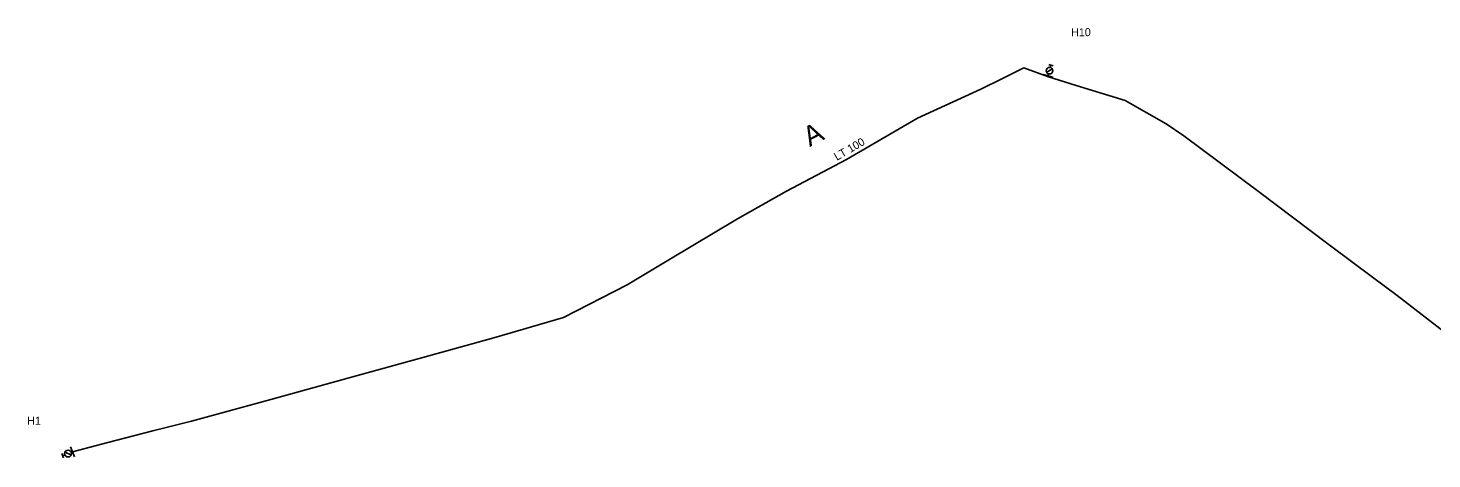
# Model space of a CAD drawing. Extents: x -574447 to -573745, y -1188179 to -1187219.
# Drawn here: x -574446.6 to -574095.8, y -1188024.4 to -1187916.7 of the extents above; entities that cross this region are included whole.
import ezdxf

# ---------------------------------------------------------------- set-up
doc = ezdxf.new("R2010")
doc.units = 0
for name, color, linetype in [('Vrstva 1', 7, 'Continuous'), ('Vrstva 15', 7, 'Continuous'), ('Vrstva 25', 7, 'Continuous'), ('Vrstva 29', 7, 'Continuous'), ('Vrstva 35', 7, 'Continuous')]:
    doc.layers.add(name, color=color, linetype=linetype)

# ---------------------------------------------------------------- blocks, each defined once
blk = doc.blocks.new('160')
at = {"layer": 'Vrstva 1'}
blk.add_circle((0, 0), 0.0458, dxfattribs=at)
blk = doc.blocks.new('133')
at = {"layer": 'Vrstva 1'}
for p, q in [((0.28, 0), (0, 0)), ((0.54, 0.58), (1.7, -0.58)), ((1.94, 0), (2.52, 0)), ((2.52, 0.58), (2.52, -0.58))]:
    blk.add_line(p, q, dxfattribs=at)
blk.add_circle((1.105, 0.003), 0.825, dxfattribs=at)
blk = doc.blocks.new('150')
at = {"layer": 'Vrstva 1'}
blk.add_line((0, 1.27), (0, -1.27), dxfattribs=at)

msp = doc.modelspace()

# ---------------------------------------------------------------- linework, layer by layer
at = {"layer": 'Vrstva 15'}
msp.add_lwpolyline([(-574091.983, -1187993.214), (-574098.224, -1187988.413), (-574104.465, -1187983.612), (-574110.637, -1187978.99), (-574121.46, -1187970.886), (-574139.531, -1187957.354), (-574157.8, -1187943.678), (-574162.274, -1187940.666), (-574172.481, -1187934.845), (-574184.71, -1187931.088), (-574191.923, -1187928.872), (-574197.834, -1187926.696), (-574203.171, -1187929.354), (-574208.508, -1187932.013), (-574224.353, -1187939.236), (-574235.54, -1187945.755), (-574242.107, -1187949.582), (-574257.1, -1187957.516), (-574269.343, -1187964.428), (-574286.477, -1187974.686), (-574296.915, -1187980.934), (-574312.83, -1187989.13), (-574330.215, -1187994.155), (-574350.38, -1187999.717), (-574366.759, -1188004.24), (-574385.959, -1188009.547), (-574405.79, -1188015.029), (-574415.501, -1188017.456), (-574426.705, -1188020.361), (-574435.566, -1188022.658)], dxfattribs=at)
at = {"layer": 'Vrstva 25'}
for p, q in [((-574191.845, -1187928.896), (-574191.716, -1187928.459)), ((-574435.566, -1188022.658), (-574435.59, -1188022.665))]:
    msp.add_line(p, q, dxfattribs=at)

# ---------------------------------------------------------------- block references
for name, p, xscale, yscale, rotation in [('133', (-574191.716, -1187928.459), 0.9999999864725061, 0.9999999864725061, 74.0000013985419), ('150', (-574191.78, -1187928.678), 0.9999999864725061, 0.9999999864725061, 74.0000013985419), ('133', (-574435.59, -1188022.665), 1.0365458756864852, 1.0365458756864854, -158.02850914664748), ('150', (-574435.573, -1188022.66), 1.035124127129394, 1.0351241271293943, 22.503654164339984)]:
    msp.add_blockref(name, p, dxfattribs=dict(at, xscale=xscale, yscale=yscale, rotation=rotation))
at = {"layer": 'Vrstva 29', "xscale": 1.0009847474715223, "yscale": 1.0009847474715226, "rotation": -165.7756737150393}
msp.add_blockref('160', (-574435.566, -1188022.658), dxfattribs=at)

# ---------------------------------------------------------------- texts
at = {"layer": 'Vrstva 25'}
for s, p in [('H10', (-574185.986, -1187918.779)), ('H1', (-574446.86, -1188015.885))]:
    msp.add_text(s, height=2, dxfattribs=at).set_placement(p)
at = {"layer": 'Vrstva 35'}
for s, height, rotation, p in [('A', 5, 27.89, (-574251.29, -1187946.523)), ('LT 100', 2, 30.23, (-574244.516, -1187949.948))]:
    msp.add_text(s, height=height, rotation=rotation, dxfattribs=at).set_placement(p)

doc.saveas('drawing.dxf')
